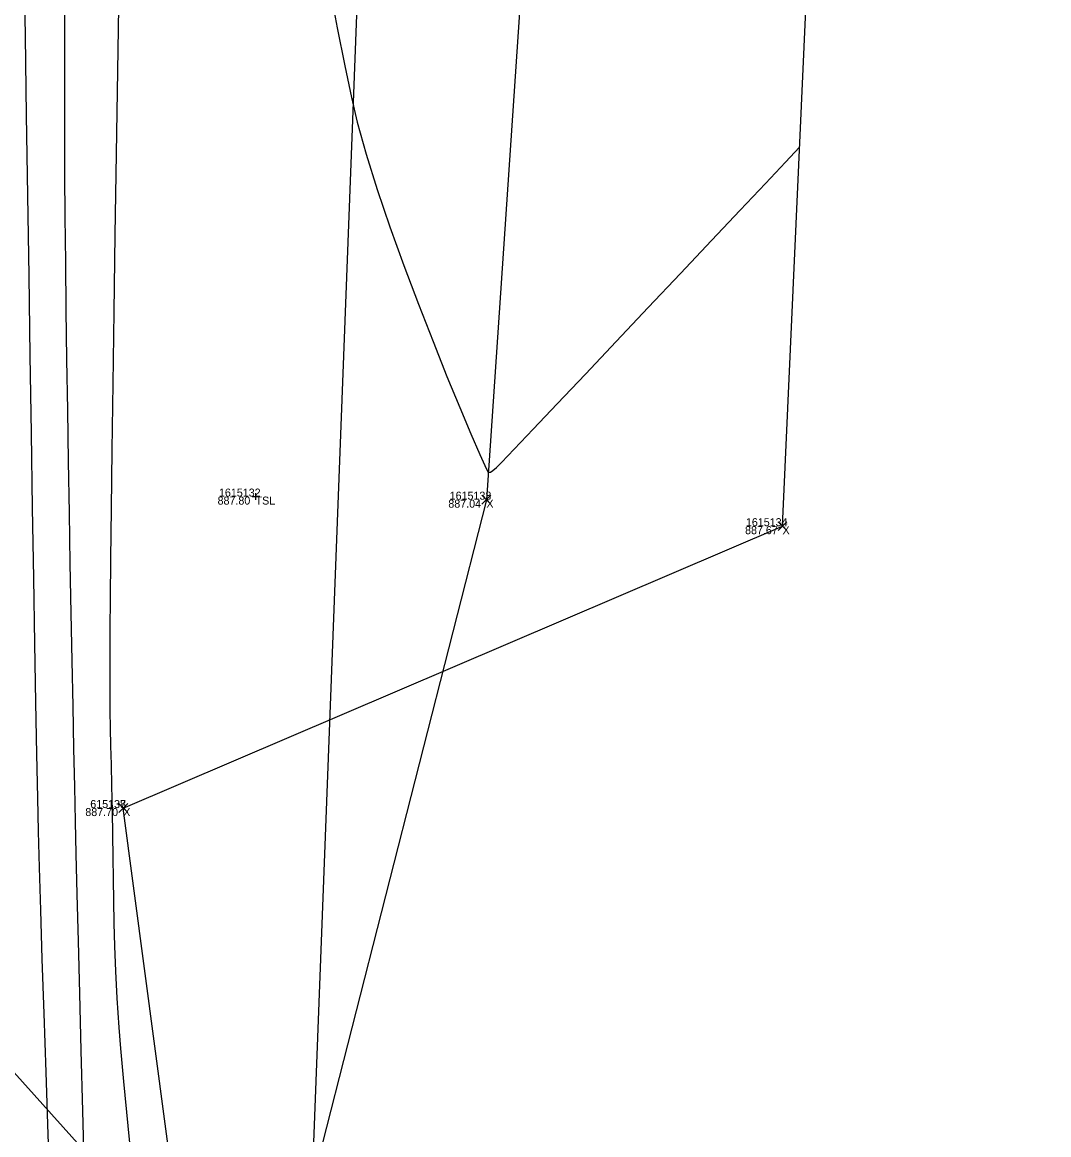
# Model space of a CAD drawing. Extents: x 1957117 to 1971063, y 701601 to 715861.
# Drawn here: x 1962717.89 to 1962762.81, y 702074.62 to 702123.29 of the extents above; entities that cross this region are included whole.
import ezdxf

# ---------------------------------------------------------------- set-up
doc = ezdxf.new("R2010")
doc.units = 0
for name, color, linetype in [('AP_X_Lights', 7, 'Continuous'), ('DT_X_Break_Line', 7, 'Continuous'), ('DT_X_Contour_Major', 7, 'Continuous'), ('DT_X_Contour_Minor', 7, 'Continuous'), ('DT_X_TIN_Hull', 7, 'Continuous'), ('PV_P_Drive', 7, 'Continuous'), ('PV_P_Shoulder', 7, 'Continuous'), ('RS_Raster1', 7, 'Continuous'), ('RW_X_Esmt_RR', 7, 'Continuous'), ('SC_Scratch1', 7, 'Continuous'), ('VG_X_Tree_Line_Rt', 7, 'Continuous')]:
    doc.layers.add(name, color=color, linetype=linetype)

msp = doc.modelspace()

# ---------------------------------------------------------------- linework, layer by layer
at = {"layer": 'AP_X_Lights'}
for p, q in [((1962738.003, 702102.213), (1962738.391, 702102.603)), ((1962738.003, 702102.603), (1962738.391, 702102.213)), ((1962750.963, 702101.053), (1962751.351, 702101.443)), ((1962750.963, 702101.443), (1962751.351, 702101.053)), ((1962722.113, 702088.722), (1962722.501, 702089.112)), ((1962722.113, 702089.112), (1962722.501, 702088.722)), ((1962722.113, 702088.721), (1962722.501, 702089.111)), ((1962722.113, 702089.111), (1962722.501, 702088.721))]:
    msp.add_line(p, q, dxfattribs=at)
at = {"layer": 'DT_X_Break_Line'}
msp.add_lwpolyline([(1962752.132, 702702.919), (1962747.065, 702649.147), (1962745.48, 702606.97), (1962743.008, 702552.829), (1962740.623, 702503.302), (1962740.641, 702452.933), (1962736.982, 702403.388), (1962741.529, 702352.919), (1962733.397, 702302.963), (1962742.046, 702251.987), (1962742.053, 702202.145), (1962741.582, 702152.179), (1962738.197, 702102.408), (1962725.619, 702053.061)], dxfattribs=at)
at = {"layer": 'DT_X_Contour_Major'}
msp.add_lwpolyline([(1962717.963, 702126.041), (1962718.011, 702122.685), (1962718.062, 702119.228), (1962718.115, 702115.716), (1962718.169, 702112.196), (1962718.223, 702108.714), (1962718.277, 702105.319), (1962718.329, 702102.056), (1962718.38, 702098.973), (1962718.429, 702096.116), (1962718.474, 702093.531), (1962718.516, 702091.267), (1962718.553, 702089.37), (1962718.584, 702087.886), (1962718.625, 702086.322), (1962718.68, 702084.447), (1962718.748, 702082.3), (1962718.827, 702079.923), (1962718.915, 702077.355), (1962719.01, 702074.637), (1962719.11, 702071.809)], dxfattribs=at)
msp.add_lwpolyline([(1962717.963, 702126.041), (1962718.011, 702122.685), (1962718.062, 702119.228), (1962718.115, 702115.716), (1962718.169, 702112.196), (1962718.223, 702108.714), (1962718.277, 702105.319), (1962718.329, 702102.056), (1962718.38, 702098.973), (1962718.429, 702096.116), (1962718.474, 702093.531), (1962718.516, 702091.267), (1962718.553, 702089.37), (1962718.584, 702087.886), (1962718.625, 702086.322), (1962718.68, 702084.447), (1962718.748, 702082.3), (1962718.827, 702079.923), (1962718.915, 702077.355), (1962719.01, 702074.637), (1962719.11, 702071.809)], dxfattribs=at)
at = {"layer": 'DT_X_Contour_Minor'}
for points in [[(1962719.753, 702124.68), (1962719.743, 702122.88), (1962719.736, 702121.252), (1962719.732, 702119.824), (1962719.733, 702118.319), (1962719.741, 702116.629), (1962719.756, 702114.78), (1962719.776, 702112.799), (1962719.801, 702110.712), (1962719.83, 702108.545), (1962719.863, 702106.325), (1962719.898, 702104.078), (1962719.936, 702101.832), (1962719.975, 702099.612), (1962720.016, 702097.445), (1962720.056, 702095.358), (1962720.095, 702093.377), (1962720.134, 702091.528), (1962720.17, 702089.838), (1962720.204, 702088.334), (1962720.237, 702086.907), (1962720.279, 702085.147), (1962720.329, 702083.099), (1962720.386, 702080.806), (1962720.45, 702078.312), (1962720.519, 702075.66), (1962720.593, 702072.894)], [(1962719.753, 702124.68), (1962719.743, 702122.88), (1962719.736, 702121.252), (1962719.732, 702119.824), (1962719.733, 702118.319), (1962719.741, 702116.629), (1962719.756, 702114.78), (1962719.776, 702112.799), (1962719.801, 702110.712), (1962719.83, 702108.545), (1962719.863, 702106.325), (1962719.898, 702104.078), (1962719.936, 702101.832), (1962719.975, 702099.612), (1962720.016, 702097.445), (1962720.056, 702095.358), (1962720.095, 702093.377), (1962720.134, 702091.528), (1962720.17, 702089.838), (1962720.204, 702088.334), (1962720.237, 702086.907), (1962720.279, 702085.147), (1962720.329, 702083.099), (1962720.386, 702080.806), (1962720.45, 702078.312), (1962720.519, 702075.66), (1962720.593, 702072.894)], [(1962722.119, 702124.868), (1962722.058, 702121.174), (1962722, 702117.534), (1962721.946, 702114.001), (1962721.897, 702110.629), (1962721.852, 702107.472), (1962721.813, 702104.582), (1962721.78, 702102.014), (1962721.753, 702099.822), (1962721.732, 702098.058), (1962721.719, 702096.777), (1962721.714, 702096.031), (1962721.714, 702094.928), (1962721.718, 702093.993), (1962721.727, 702093.172), (1962721.739, 702092.407), (1962721.755, 702091.642), (1962721.774, 702090.82), (1962721.797, 702089.886), (1962721.823, 702088.783), (1962721.843, 702087.745), (1962721.857, 702086.761), (1962721.868, 702085.806), (1962721.881, 702084.855), (1962721.9, 702083.885), (1962721.929, 702082.869), (1962721.971, 702081.784), (1962722.03, 702080.606), (1962722.111, 702079.309), (1962722.185, 702078.401), (1962722.318, 702076.948), (1962722.505, 702075.011), (1962722.737, 702072.655)], [(1962722.119, 702124.868), (1962722.058, 702121.174), (1962722, 702117.534), (1962721.946, 702114.001), (1962721.897, 702110.629), (1962721.852, 702107.472), (1962721.813, 702104.582), (1962721.78, 702102.014), (1962721.753, 702099.822), (1962721.732, 702098.058), (1962721.719, 702096.777), (1962721.714, 702096.031), (1962721.714, 702094.928), (1962721.718, 702093.993), (1962721.727, 702093.172), (1962721.739, 702092.407), (1962721.755, 702091.642), (1962721.774, 702090.82), (1962721.797, 702089.886), (1962721.823, 702088.783), (1962721.843, 702087.745), (1962721.857, 702086.761), (1962721.868, 702085.806), (1962721.881, 702084.855), (1962721.9, 702083.885), (1962721.929, 702082.869), (1962721.971, 702081.784), (1962722.03, 702080.606), (1962722.111, 702079.309), (1962722.185, 702078.401), (1962722.318, 702076.948), (1962722.505, 702075.011), (1962722.737, 702072.655)], [(1962731.325, 702124.93), (1962731.675, 702123.045), (1962732, 702121.389), (1962732.293, 702120), (1962732.547, 702118.918), (1962732.933, 702117.526), (1962733.419, 702115.982), (1962733.98, 702114.339), (1962734.591, 702112.647), (1962735.227, 702110.96), (1962735.863, 702109.327), (1962736.473, 702107.803), (1962737.034, 702106.437), (1962737.52, 702105.283), (1962737.906, 702104.391), (1962738.126, 702103.902), (1962738.231, 702103.683), (1962738.269, 702103.614), (1962738.278, 702103.604), (1962738.312, 702103.597), (1962738.378, 702103.61), (1962738.481, 702103.678), (1962738.637, 702103.812), (1962738.855, 702104.035), (1962739.409, 702104.615), (1962740.242, 702105.491), (1962741.3, 702106.608), (1962742.528, 702107.905), (1962743.872, 702109.325), (1962745.276, 702110.811), (1962746.687, 702112.303), (1962748.048, 702113.743), (1962749.305, 702115.074), (1962750.404, 702116.236), (1962751.289, 702117.173), (1962751.906, 702117.825)], [(1962731.325, 702124.93), (1962731.675, 702123.045), (1962732, 702121.389), (1962732.293, 702120), (1962732.547, 702118.918), (1962732.933, 702117.526), (1962733.419, 702115.982), (1962733.98, 702114.339), (1962734.591, 702112.647), (1962735.227, 702110.96), (1962735.863, 702109.327), (1962736.473, 702107.803), (1962737.034, 702106.437), (1962737.52, 702105.283), (1962737.906, 702104.391), (1962738.126, 702103.902), (1962738.231, 702103.683), (1962738.269, 702103.614), (1962738.278, 702103.604), (1962738.312, 702103.597), (1962738.378, 702103.61), (1962738.481, 702103.678), (1962738.637, 702103.812), (1962738.855, 702104.035), (1962739.409, 702104.615), (1962740.242, 702105.491), (1962741.3, 702106.608), (1962742.528, 702107.905), (1962743.872, 702109.325), (1962745.276, 702110.811), (1962746.687, 702112.303), (1962748.048, 702113.743), (1962749.305, 702115.074), (1962750.404, 702116.236), (1962751.289, 702117.173), (1962751.906, 702117.825)]]:
    msp.add_lwpolyline(points, dxfattribs=at)
at = {"layer": 'DT_X_TIN_Hull'}
msp.add_lwpolyline([(1962657.931, 702308.011), (1962655.854, 702258.355), (1962653.64, 702207.97), (1962651.503, 702157.712), (1962649.771, 702107.746), (1962674.688, 702087.643), (1962671.405, 702038.683), (1962651.95, 702019.751), (1962598.276, 702023.522), (1962596.236, 701997.877), (1962651.443, 701993.881), (1962750.651, 701987.35), (1962803.275, 701984.672), (1962804.883, 701997.219), (1962805.914, 702009.441), (1962753.632, 702013.572), (1962730.2, 702029.616), (1962722.307, 702088.916), (1962751.157, 702101.248), (1962753.404, 702150.955), (1962757.576, 702251.621), (1962759.026, 702351.713)], dxfattribs=at)
at = {"layer": 'PV_P_Drive'}
for p, q in [((1962728.099, 702102.689), (1962728.099, 702102.397)), ((1962727.953, 702102.543), (1962728.245, 702102.543)), ((1962728.099, 702102.543), (1962728.099, 702102.543))]:
    msp.add_line(p, q, dxfattribs=at)
at = {"layer": 'RW_X_Esmt_RR'}
msp.add_lwpolyline([(1962729.176, 702035.621), (1962771.351, 703140.475)], dxfattribs=at)
at = {"layer": 'VG_X_Tree_Line_Rt'}
msp.add_lwpolyline([(1962654.57, 702149.712), (1962660.569, 702142.56), (1962659.212, 702133.988), (1962654.978, 702118.048), (1962660.346, 702106.792), (1962660.346, 702106.792), (1962654.43, 702101.553), (1962652.311, 702066.915), (1962667.755, 702070.232), (1962673.804, 702062.151), (1962692.583, 702066.445), (1962699.739, 702079.35), (1962700.636, 702088.753), (1962713.933, 702088.72), (1962716.232, 702078.774), (1962721.334, 702073.125), (1962719.433, 702062.796), (1962718.435, 702051.422), (1962724.351, 702042.104), (1962737.296, 702036.111), (1962751.323, 702040.439)], dxfattribs=at)

# ---------------------------------------------------------------- texts
at = {"layer": 'PV_P_Shoulder'}
for s, p in [('887.80', (1962726.435, 702102.193)), ('887.04', (1962736.533, 702102.058)), ('887.67', (1962749.517, 702100.898)), ('887.70', (1962720.648, 702088.567)), ('887.70', (1962720.648, 702088.566))]:
    msp.add_text(s, height=0.35, dxfattribs=at).set_placement(p)
at = {"layer": 'RS_Raster1'}
for s, p in [('1615132', (1962726.496, 702102.543)), ('1615133', (1962736.591, 702102.408)), ('1615134', (1962749.554, 702101.248)), ('615138', (1962720.863, 702088.917)), ('615137', (1962720.866, 702088.916))]:
    msp.add_text(s, height=0.35, dxfattribs=at).set_placement(p)
at = {"layer": 'SC_Scratch1'}
for s, p in [('TSL', (1962728.099, 702102.193)), ('X', (1962738.197, 702102.058)), ('X', (1962751.157, 702100.898)), ('X', (1962722.307, 702088.567)), ('X', (1962722.307, 702088.566))]:
    msp.add_text(s, height=0.35, dxfattribs=at).set_placement(p)

doc.saveas('drawing.dxf')
